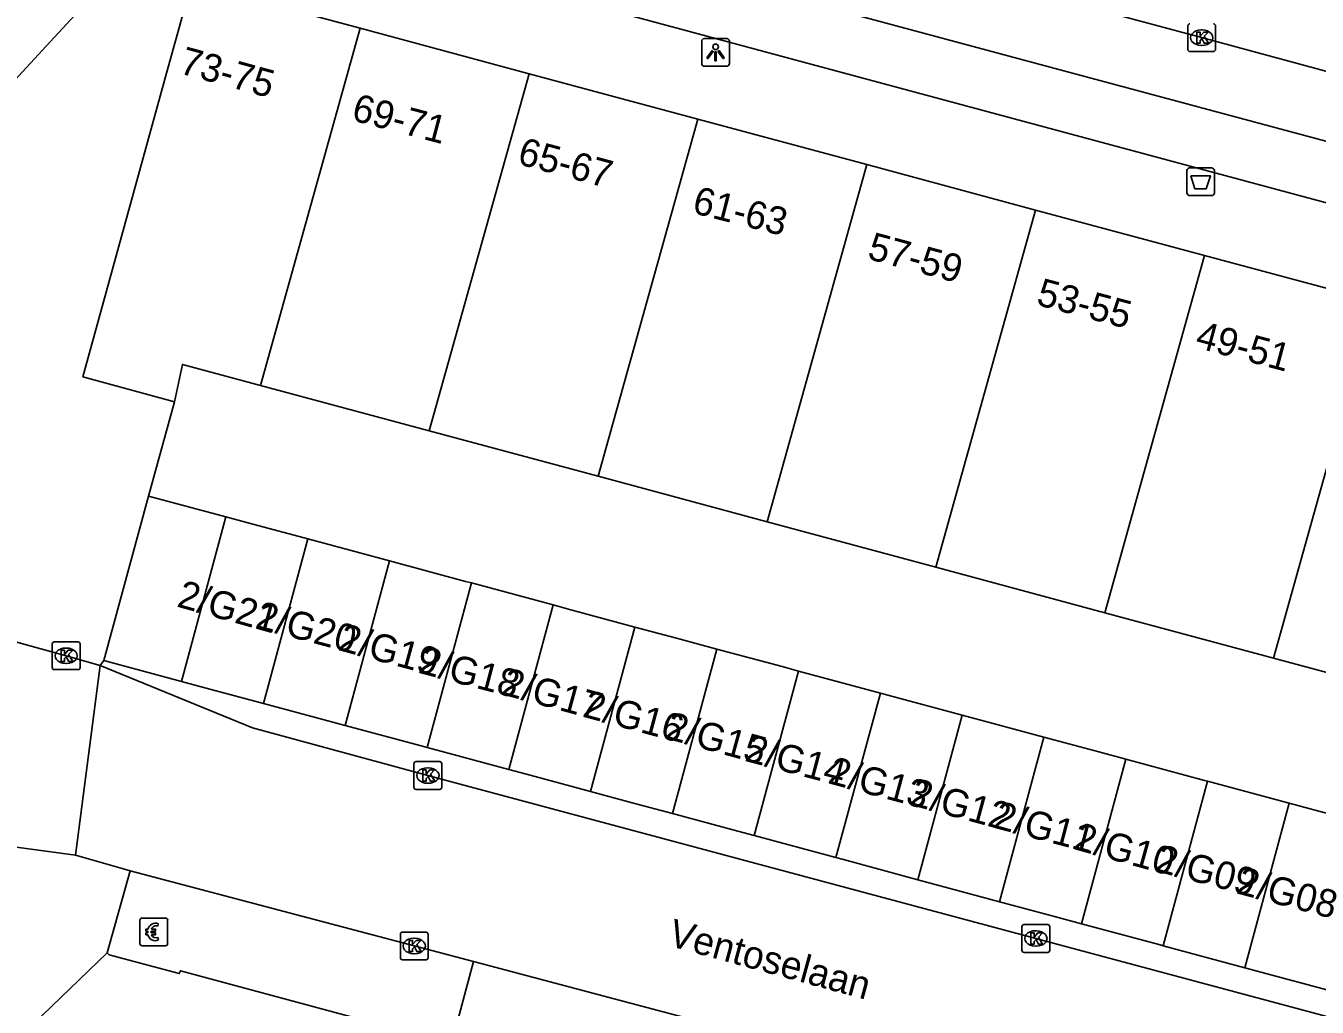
# Model space of a CAD drawing. Extents: x 160676 to 161153, y 383244 to 383713.
# Drawn here: x 160733.93 to 160780.46, y 383560.56 to 383595.93 of the extents above; entities that cross this region are included whole.
import ezdxf

# ---------------------------------------------------------------- set-up
doc = ezdxf.new("R2010")
doc.units = 0
for name, color, linetype in [('IMGEO_Afvalbak', 7, 'Continuous'), ('IMGEO_Betaalautomaat', 7, 'Continuous'), ('IMGEO_Fietspad_gesloten', 7, 'Continuous'), ('IMGEO_Kolk', 7, 'Continuous'), ('IMGEO_Lichtpunt', 7, 'Continuous'), ('IMGEO_Muur', 7, 'Continuous'), ('IMGEO_Openbare_ruimte_label', 7, 'Continuous'), ('IMGEO_Pand', 7, 'Continuous'), ('IMGEO_Pand_nummerreeks', 7, 'Continuous'), ('IMGEO_Parkeervlak_open', 7, 'Continuous'), ('IMGEO_Rijbaan_lokaal_open', 7, 'Continuous'), ('IMGEO_Voetpad_gesloten', 7, 'Continuous'), ('IMGEO_Voetpad_open', 7, 'Continuous')]:
    doc.layers.add(name, color=color, linetype=linetype)

msp = doc.modelspace()

# ---------------------------------------------------------------- linework, layer by layer
at = {"layer": 'IMGEO_Afvalbak'}
for p, q in [((160775.762, 383589.912), (160775.762, 383590.712)), ((160775.762, 383590.712), (160775.762, 383589.912)), ((160775.862, 383590.812), (160776.652, 383590.812)), ((160776.652, 383590.812), (160775.862, 383590.812)), ((160776.752, 383590.712), (160776.752, 383589.912)), ((160776.752, 383589.912), (160776.752, 383590.712)), ((160776.652, 383589.812), (160775.862, 383589.812)), ((160775.862, 383589.812), (160776.652, 383589.812))]:
    msp.add_line(p, q, dxfattribs=at)
msp.add_lwpolyline([(160775.905, 383590.526), (160776.609, 383590.526), (160776.46, 383590.056), (160776.054, 383590.056), (160775.905, 383590.526)], dxfattribs=at)
for centre, start, end in [((160775.862, 383590.712), 90, 180), ((160775.862, 383590.712), 90, 180), ((160776.652, 383590.712), 0, 90), ((160776.652, 383590.712), 360, 90), ((160775.862, 383589.912), 180, 270), ((160775.862, 383589.912), 180, 270), ((160776.652, 383589.912), 270, 0), ((160776.652, 383589.912), 270, 0)]:
    msp.add_arc(centre, 0.1, start, end, dxfattribs=at)
at = {"layer": 'IMGEO_Betaalautomaat'}
for p, q in [((160738.042, 383562.848), (160738.042, 383563.689)), ((160738.042, 383563.689), (160738.042, 383562.848)), ((160738.117, 383563.772), (160738.958, 383563.772)), ((160738.958, 383563.772), (160738.117, 383563.772)), ((160738.704, 383563.577), (160738.687, 383563.477)), ((160739.041, 383563.698), (160739.041, 383562.857)), ((160739.041, 383562.857), (160739.041, 383563.698)), ((160738.325, 383563.236), (160738.325, 383563.304)), ((160738.446, 383563.304), (160738.446, 383563.236)), ((160738.967, 383562.773), (160738.126, 383562.773)), ((160738.126, 383562.773), (160738.967, 383562.773)), ((160738.691, 383563.071), (160738.713, 383562.984))]:
    msp.add_line(p, q, dxfattribs=at)
for points in [[(160738.325, 383563.304), (160738.256, 383563.304), (160738.256, 383563.373), (160738.335, 383563.373)], [(160738.33, 383563.167), (160738.256, 383563.167), (160738.256, 383563.236), (160738.325, 383563.236)], [(160738.457, 383563.373), (160738.604, 383563.373), (160738.604, 383563.304), (160738.446, 383563.304)], [(160738.446, 383563.236), (160738.604, 383563.236), (160738.604, 383563.167), (160738.46, 383563.167)]]:
    msp.add_lwpolyline(points, dxfattribs=at)
for centre, radius, start, end in [((160738.12, 383563.695), 0.0779, 92.4484, 184.2845), ((160738.12, 383563.695), 0.0779, 92.4484, 184.2845), ((160738.618, 383563.297), 0.293, 73.014, 165.0139), ((160738.964, 383563.695), 0.0779, 2.4484, 94.2845), ((160738.964, 383563.695), 0.0779, 2.4484, 94.2845), ((160738.591, 383563.222), 0.267, 191.8096, 297.0389), ((160738.624, 383563.31), 0.179, 69.3236, 159.5683), ((160738.624, 383563.237), 0.179, 202.7625, 291.8693), ((160738.12, 383562.851), 0.0779, 182.4484, 274.2845), ((160738.12, 383562.851), 0.0779, 182.4484, 274.2845), ((160738.964, 383562.851), 0.0779, 272.4484, 4.2845), ((160738.964, 383562.851), 0.0779, 272.4484, 4.2845)]:
    msp.add_arc(centre, radius, start, end, dxfattribs=at)
at = {"layer": 'IMGEO_Fietspad_gesloten'}
for points in [[(160904.417, 383556.04), (160869.912, 383565.633), (160851.652, 383570.489), (160741.54, 383600.127)], [(160720.294, 383579.626), (160734.953, 383595.515), (160738.597, 383599.464)], [(160753.356, 383599.164), (160754.374, 383598.874), (160872.54, 383567.128), (160873.601, 383566.834)]]:
    msp.add_lwpolyline(points, dxfattribs=at)
at = {"layer": 'IMGEO_Kolk'}
for p, q in [((160775.795, 383595.08), (160775.795, 383595.932)), ((160776.283, 383595.786), (160776.308, 383595.786)), ((160776.796, 383595.932), (160776.796, 383595.08)), ((160776.306, 383595.226), (160776.281, 383595.226)), ((160776.722, 383595.006), (160775.87, 383595.006)), ((160734.882, 383572.798), (160734.882, 383573.65)), ((160734.957, 383573.724), (160735.809, 383573.724)), ((160735.37, 383573.504), (160735.395, 383573.504)), ((160735.883, 383573.65), (160735.883, 383572.798)), ((160735.393, 383572.944), (160735.368, 383572.944)), ((160735.809, 383572.724), (160734.957, 383572.724)), ((160747.916, 383568.482), (160747.916, 383569.334)), ((160747.991, 383569.408), (160748.843, 383569.408)), ((160748.404, 383569.188), (160748.429, 383569.188)), ((160748.917, 383569.334), (160748.917, 383568.482)), ((160748.843, 383568.408), (160747.991, 383568.408)), ((160748.427, 383568.628), (160748.402, 383568.628)), ((160747.424, 383562.339), (160747.424, 383563.191)), ((160747.499, 383563.265), (160748.351, 383563.265)), ((160748.425, 383563.191), (160748.425, 383562.339)), ((160769.821, 383562.608), (160769.821, 383563.46)), ((160769.896, 383563.534), (160770.748, 383563.534)), ((160770.309, 383563.314), (160770.334, 383563.314)), ((160770.822, 383563.46), (160770.822, 383562.608)), ((160747.912, 383563.045), (160747.937, 383563.045)), ((160770.332, 383562.754), (160770.307, 383562.754)), ((160748.351, 383562.265), (160747.499, 383562.265)), ((160747.935, 383562.485), (160747.91, 383562.485)), ((160770.748, 383562.534), (160769.896, 383562.534))]:
    msp.add_line(p, q, dxfattribs=at)
for points in [[(160775.795, 383595.08), (160775.795, 383595.932)], [(160776.116, 383595.706), (160776.239, 383595.706), (160776.239, 383595.555), (160776.369, 383595.706), (160776.533, 383595.706), (160776.387, 383595.555), (160776.54, 383595.306), (160776.388, 383595.306), (160776.303, 383595.47), (160776.239, 383595.403), (160776.239, 383595.306), (160776.116, 383595.306), (160776.116, 383595.706)], [(160776.796, 383595.932), (160776.796, 383595.08)], [(160776.722, 383595.006), (160775.87, 383595.006)], [(160734.882, 383572.798), (160734.882, 383573.65)], [(160734.957, 383573.724), (160735.809, 383573.724)], [(160735.203, 383573.424), (160735.326, 383573.424), (160735.326, 383573.273), (160735.456, 383573.424), (160735.62, 383573.424), (160735.474, 383573.273), (160735.627, 383573.024), (160735.475, 383573.024), (160735.39, 383573.188), (160735.326, 383573.121), (160735.326, 383573.024), (160735.203, 383573.024), (160735.203, 383573.424)], [(160735.883, 383573.65), (160735.883, 383572.798)], [(160735.809, 383572.724), (160734.957, 383572.724)], [(160747.916, 383568.482), (160747.916, 383569.334)], [(160747.991, 383569.408), (160748.843, 383569.408)], [(160748.917, 383569.334), (160748.917, 383568.482)], [(160748.237, 383569.108), (160748.36, 383569.108), (160748.36, 383568.957), (160748.49, 383569.108), (160748.654, 383569.108), (160748.508, 383568.957), (160748.661, 383568.708), (160748.509, 383568.708), (160748.424, 383568.872), (160748.36, 383568.805), (160748.36, 383568.708), (160748.237, 383568.708), (160748.237, 383569.108)], [(160748.843, 383568.408), (160747.991, 383568.408)], [(160747.424, 383562.339), (160747.424, 383563.191)], [(160747.499, 383563.265), (160748.351, 383563.265)], [(160748.425, 383563.191), (160748.425, 383562.339)], [(160769.821, 383562.608), (160769.821, 383563.46)], [(160769.896, 383563.534), (160770.748, 383563.534)], [(160770.142, 383563.234), (160770.265, 383563.234), (160770.265, 383563.083), (160770.395, 383563.234), (160770.559, 383563.234), (160770.413, 383563.083), (160770.566, 383562.834), (160770.414, 383562.834), (160770.329, 383562.998), (160770.265, 383562.931), (160770.265, 383562.834), (160770.142, 383562.834), (160770.142, 383563.234)], [(160770.822, 383563.46), (160770.822, 383562.608)], [(160747.745, 383562.965), (160747.868, 383562.965), (160747.868, 383562.814), (160747.998, 383562.965), (160748.162, 383562.965), (160748.016, 383562.814), (160748.169, 383562.565), (160748.017, 383562.565), (160747.932, 383562.729), (160747.868, 383562.662), (160747.868, 383562.565), (160747.745, 383562.565), (160747.745, 383562.965)], [(160748.351, 383562.265), (160747.499, 383562.265)], [(160770.748, 383562.534), (160769.896, 383562.534)]]:
    msp.add_lwpolyline(points, dxfattribs=at)
for centre, start, end in [((160775.872, 383595.93), 91.552, 178.448), ((160775.872, 383595.93), 91.552, 178.448), ((160776.72, 383595.93), 1.552, 88.448), ((160776.72, 383595.93), 1.552, 88.448), ((160775.872, 383595.082), 181.552, 268.448), ((160775.872, 383595.082), 181.552, 268.448), ((160776.72, 383595.082), 271.552, 358.448), ((160776.72, 383595.082), 271.552, 358.448), ((160734.959, 383573.648), 91.552, 178.448), ((160734.959, 383573.648), 91.552, 178.448), ((160735.807, 383573.648), 1.552, 88.448), ((160735.807, 383573.648), 1.552, 88.448), ((160734.959, 383572.8), 181.552, 268.448), ((160734.959, 383572.8), 181.552, 268.448), ((160735.807, 383572.8), 271.552, 358.448), ((160735.807, 383572.8), 271.552, 358.448), ((160747.993, 383569.332), 91.552, 178.448), ((160747.993, 383569.332), 91.552, 178.448), ((160748.841, 383569.332), 1.552, 88.448), ((160748.841, 383569.332), 1.552, 88.448), ((160747.993, 383568.484), 181.552, 268.448), ((160747.993, 383568.484), 181.552, 268.448), ((160748.841, 383568.484), 271.552, 358.448), ((160748.841, 383568.484), 271.552, 358.448), ((160747.501, 383563.189), 91.552, 178.448), ((160747.501, 383563.189), 91.552, 178.448), ((160748.349, 383563.189), 1.552, 88.448), ((160748.349, 383563.189), 1.552, 88.448), ((160769.898, 383563.458), 91.552, 178.448), ((160769.898, 383563.458), 91.552, 178.448), ((160770.746, 383563.458), 1.552, 88.448), ((160770.746, 383563.458), 1.552, 88.448), ((160747.501, 383562.341), 181.552, 268.448), ((160747.501, 383562.341), 181.552, 268.448), ((160748.349, 383562.341), 271.552, 358.448), ((160748.349, 383562.341), 271.552, 358.448), ((160769.898, 383562.61), 181.552, 268.448), ((160769.898, 383562.61), 181.552, 268.448), ((160770.746, 383562.61), 271.552, 358.448), ((160770.746, 383562.61), 271.552, 358.448)]:
    msp.add_arc(centre, 0.0765, start, end, dxfattribs=at)
for centre, major_axis, ratio, start_param, end_param in [((160776.282, 383595.506), (-0.387, 0.002), 0.722429, 4.712389, 7.853982), ((160776.307, 383595.506), (-0.39, 0.002), 0.717154, 1.570796, 4.712389), ((160735.369, 383573.224), (-0.387, 0.002), 0.722429, 4.712389, 7.853982), ((160735.394, 383573.224), (-0.39, 0.002), 0.717154, 1.570796, 4.712389), ((160748.403, 383568.908), (-0.387, 0.002), 0.722429, 4.712389, 7.853982), ((160748.428, 383568.908), (-0.39, 0.002), 0.717154, 1.570796, 4.712389), ((160770.308, 383563.034), (-0.387, 0.002), 0.722429, 4.712389, 7.853982), ((160770.333, 383563.034), (-0.39, 0.002), 0.717154, 1.570796, 4.712389), ((160747.911, 383562.765), (-0.387, 0.002), 0.722429, 4.712389, 7.853982), ((160747.936, 383562.765), (-0.39, 0.002), 0.717154, 1.570796, 4.712389)]:
    msp.add_ellipse(centre, major_axis=major_axis, ratio=ratio, start_param=start_param, end_param=end_param, dxfattribs=at)
at = {"layer": 'IMGEO_Lichtpunt'}
for p, q in [((160758.283, 383595.376), (160758.283, 383594.569)), ((160758.283, 383595.376), (160758.283, 383594.569)), ((160759.185, 383595.471), (160758.377, 383595.471)), ((160759.185, 383595.471), (160758.377, 383595.471)), ((160759.279, 383594.569), (160759.279, 383595.376)), ((160759.279, 383594.569), (160759.279, 383595.376)), ((160758.377, 383594.475), (160759.185, 383594.475)), ((160758.377, 383594.475), (160759.185, 383594.475))]:
    msp.add_line(p, q, dxfattribs=at)
for points in [[(160758.657, 383595.04), (160758.696, 383595.012), (160758.508, 383594.75), (160758.47, 383594.777), (160758.657, 383595.04)], [(160758.759, 383594.992), (160758.806, 383594.992), (160758.806, 383594.67), (160758.759, 383594.67), (160758.759, 383594.992)], [(160758.869, 383595.012), (160758.907, 383595.039), (160759.094, 383594.777), (160759.055, 383594.749), (160758.869, 383595.012)]]:
    msp.add_lwpolyline(points, dxfattribs=at)
msp.add_circle((160758.782, 383595.174), 0.0994, dxfattribs=at)
for centre, start, end in [((160758.377, 383595.376), 90, 180), ((160758.377, 383595.376), 90, 180), ((160759.185, 383595.376), 0, 90), ((160759.185, 383595.376), 0, 90), ((160758.377, 383594.569), 180, 270), ((160758.377, 383594.569), 180, 270), ((160759.185, 383594.569), 270, 0), ((160759.185, 383594.569), 270, 360)]:
    msp.add_arc(centre, 0.0946, start, end, dxfattribs=at)
at = {"layer": 'IMGEO_Muur'}
msp.add_lwpolyline([(160739.286, 383582.381), (160738.356, 383578.98)], dxfattribs=at)
at = {"layer": 'IMGEO_Pand'}
for points in [[(160739.966, 383597.73), (160739, 383594.22), (160735.987, 383583.276), (160739.286, 383582.381)], [(160739.966, 383597.73), (160740.363, 383597.607), (160740.309, 383597.372), (160745.98, 383595.844)], [(160745.98, 383595.844), (160742.385, 383582.972)], [(160745.98, 383595.844), (160752.064, 383594.206)], [(160748.468, 383581.333), (160752.064, 383594.206)], [(160752.064, 383594.206), (160758.147, 383592.567)], [(160758.147, 383592.567), (160754.552, 383579.694)], [(160758.147, 383592.567), (160764.231, 383590.928)], [(160764.231, 383590.928), (160760.635, 383578.056)], [(160764.231, 383590.928), (160770.314, 383589.29)], [(160766.719, 383576.417), (160770.314, 383589.29)], [(160770.314, 383589.29), (160776.398, 383587.651)], [(160776.398, 383587.651), (160772.802, 383574.778)], [(160776.398, 383587.651), (160782.481, 383586.013)], [(160782.481, 383586.013), (160778.885, 383573.14)], [(160742.385, 383582.972), (160739.571, 383583.729), (160739.286, 383582.381)], [(160748.468, 383581.333), (160742.385, 383582.972)], [(160754.552, 383579.694), (160748.468, 383581.333)], [(160760.635, 383578.056), (160754.552, 383579.694)], [(160736.736, 383573.058), (160738.356, 383578.98)], [(160738.356, 383578.98), (160741.141, 383578.23)], [(160741.141, 383578.23), (160739.544, 383572.301)], [(160741.141, 383578.23), (160742.158, 383577.956), (160744.089, 383577.436)], [(160766.719, 383576.417), (160760.635, 383578.056)], [(160742.492, 383571.507), (160744.089, 383577.436)], [(160744.089, 383577.436), (160745.962, 383576.932), (160747.036, 383576.642)], [(160747.036, 383576.642), (160745.439, 383570.713)], [(160747.036, 383576.642), (160749.766, 383575.907), (160749.983, 383575.849)], [(160772.802, 383574.778), (160766.719, 383576.417)], [(160748.386, 383569.919), (160749.983, 383575.849)], [(160749.983, 383575.849), (160752.93, 383575.055)], [(160752.93, 383575.055), (160751.332, 383569.125)], [(160752.93, 383575.055), (160753.571, 383574.882), (160755.877, 383574.261)], [(160778.885, 383573.14), (160772.802, 383574.778)], [(160754.279, 383568.331), (160755.877, 383574.261)], [(160755.877, 383574.261), (160757.375, 383573.857), (160758.824, 383573.467)], [(160758.824, 383573.467), (160757.226, 383567.536)], [(160758.824, 383573.467), (160761.18, 383572.833), (160761.771, 383572.673)], [(160739.544, 383572.301), (160736.736, 383573.058)], [(160784.969, 383571.501), (160778.885, 383573.14)], [(160761.771, 383572.673), (160760.173, 383566.742)], [(160761.771, 383572.673), (160764.718, 383571.88)], [(160742.492, 383571.507), (160740.561, 383572.027), (160739.544, 383572.301)], [(160745.439, 383570.713), (160744.365, 383571.002), (160742.492, 383571.507)], [(160763.12, 383565.948), (160764.718, 383571.88)], [(160764.718, 383571.88), (160764.984, 383571.808), (160767.665, 383571.086)], [(160766.067, 383565.154), (160767.665, 383571.086)], [(160767.665, 383571.086), (160768.788, 383570.783), (160770.612, 383570.292)], [(160748.386, 383569.919), (160748.169, 383569.977), (160745.439, 383570.713)], [(160770.612, 383570.292), (160769.014, 383564.36)], [(160770.612, 383570.292), (160772.593, 383569.758), (160773.558, 383569.498)], [(160751.332, 383569.125), (160748.386, 383569.919)], [(160771.961, 383563.566), (160773.558, 383569.498)], [(160773.558, 383569.498), (160776.397, 383568.734), (160776.505, 383568.704)], [(160754.279, 383568.331), (160751.974, 383568.952), (160751.332, 383569.125)], [(160776.505, 383568.704), (160774.907, 383562.772)], [(160776.505, 383568.704), (160779.452, 383567.911)], [(160757.226, 383567.536), (160755.778, 383567.927), (160754.279, 383568.331)], [(160779.452, 383567.911), (160777.854, 383561.978)], [(160779.452, 383567.911), (160780.202, 383567.709), (160782.399, 383567.117)], [(160760.173, 383566.742), (160759.582, 383566.902), (160757.226, 383567.536)], [(160763.12, 383565.948), (160760.173, 383566.742)], [(160766.067, 383565.154), (160763.386, 383565.876), (160763.12, 383565.948)], [(160769.014, 383564.36), (160767.191, 383564.851), (160766.067, 383565.154)], [(160771.961, 383563.566), (160770.995, 383563.826), (160769.014, 383564.36)], [(160774.907, 383562.772), (160774.799, 383562.801), (160771.961, 383563.566)], [(160777.854, 383561.978), (160774.907, 383562.772)], [(160736.867, 383562.513), (160734.183, 383559.937), (160733.494, 383559.276), (160728.647, 383558.534), (160727.771, 383553.734), (160724.44, 383550.502), (160724.51, 383550.431), (160725.086, 383547.856), (160724.989, 383547.833), (160725.173, 383547.028)], [(160749.27, 383559.236), (160739.499, 383561.869), (160739.458, 383561.769), (160736.936, 383562.441), (160736.867, 383562.513)], [(160780.801, 383561.184), (160778.604, 383561.776), (160777.854, 383561.978)]]:
    msp.add_lwpolyline(points, dxfattribs=at)
at = {"layer": 'IMGEO_Parkeervlak_open'}
msp.add_lwpolyline([(160782.323, 383593.874), (160776.292, 383595.507), (160765.431, 383598.425)], dxfattribs=at)
at = {"layer": 'IMGEO_Rijbaan_lokaal_open'}
for points in [[(160736.61, 383572.879), (160735.379, 383573.223), (160726.9, 383575.565)], [(160736.61, 383572.879), (160735.719, 383566.037)], [(160850.083, 383542.287), (160822.326, 383549.002), (160821.426, 383549.252), (160806.97, 383553.205), (160770.322, 383563.034), (160748.417, 383568.908), (160742.099, 383570.623), (160736.61, 383572.879)], [(160731.259, 383566.644), (160735.719, 383566.037)], [(160735.719, 383566.037), (160737.403, 383565.553), (160737.693, 383565.476)], [(160737.693, 383565.476), (160750.056, 383562.202)], [(160750.056, 383562.202), (160761.377, 383559.203)]]:
    msp.add_lwpolyline(points, dxfattribs=at)
at = {"layer": 'IMGEO_Voetpad_gesloten'}
msp.add_lwpolyline([(160749.27, 383559.236), (160750.056, 383562.202)], dxfattribs=at)
at = {"layer": 'IMGEO_Voetpad_open'}
for points in [[(160739.286, 383582.381), (160738.356, 383578.98)], [(160736.736, 383573.058), (160736.61, 383572.879)], [(160736.867, 383562.513), (160737.693, 383565.476)]]:
    msp.add_lwpolyline(points, dxfattribs=at)

# ---------------------------------------------------------------- texts
at = {"layer": 'IMGEO_Openbare_ruimte_label'}
msp.add_text('Ventoselaan', height=1, rotation=344.6997, dxfattribs=at).set_placement((160757.027, 383562.787))
at = {"layer": 'IMGEO_Pand_nummerreeks'}
for s, rotation, p in [('73-75', 344.6045, (160739.42, 383594.232)), ('69-71', 345.2564, (160745.625, 383592.537)), ('65-67', 344.8828, (160751.602, 383590.962)), ('61-63', 345.7097, (160757.9, 383589.196)), ('57-59', 344.9263, (160764.212, 383587.541)), ('53-55', 345.1206, (160770.299, 383585.884)), ('49-51', 345.0004, (160776.025, 383584.347)), ('2/G21', 344.3938, (160739.335, 383575.006)), ('2/G20', 345.0866, (160742.159, 383574.247)), ('2/G19', 344.8617, (160745.142, 383573.438)), ('2/G18', 345.2204, (160748.031, 383572.621)), ('2/G17', 344.7218, (160751.025, 383571.843)), ('2/G16', 344.8285, (160753.95, 383571.039)), ('2/G15', 344.5793, (160756.925, 383570.257)), ('2/G14', 345.1035, (160759.797, 383569.443)), ('2/G13', 344.9717, (160762.788, 383568.641)), ('2/G12', 344.8285, (160765.735, 383567.861)), ('2/G11', 345.272, (160768.755, 383567.035)), ('2/G10', 344.5038, (160771.639, 383566.266)), ('2/G09', 345.1684, (160774.574, 383565.474)), ('2/G08', 345.2204, (160777.504, 383564.669))]:
    msp.add_text(s, height=1, rotation=rotation, dxfattribs=at).set_placement(p)

doc.saveas('drawing.dxf')
